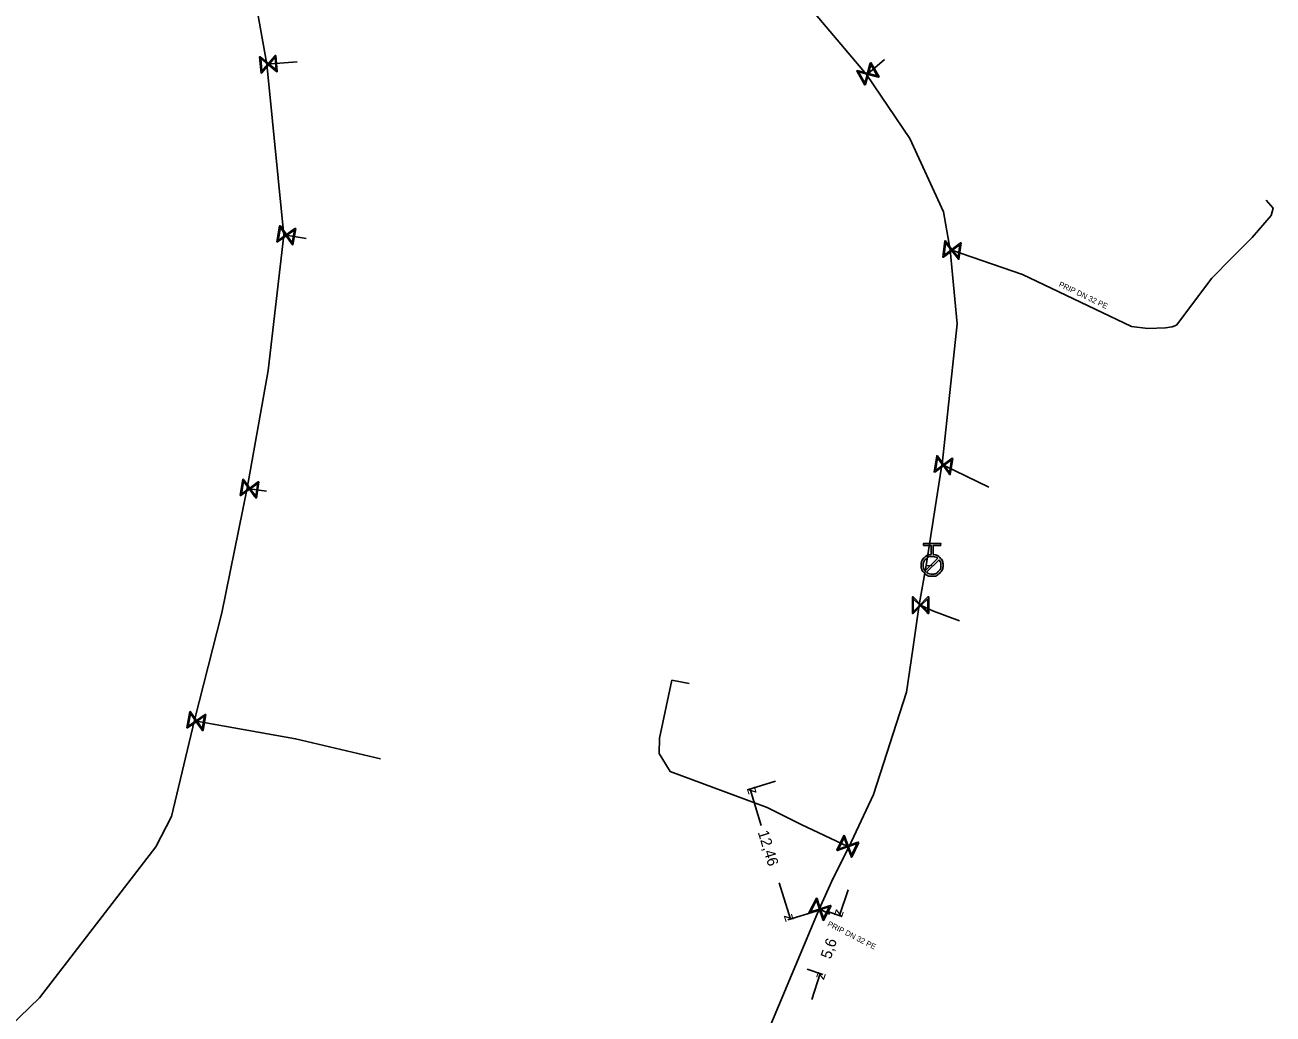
# Model space of a CAD drawing. Extents: x -641905 to -641246, y -1111750 to -1110210.
# Drawn here: x -641545.3 to -641431, y -1110496.2 to -1110405.6 of the extents above; entities that cross this region are included whole.
import ezdxf

# ---------------------------------------------------------------- set-up
doc = ezdxf.new("R2010")
doc.units = 0
for name, color, linetype in [('Default', 7, 'Continuous'), ('VP Hydrant', 7, 'Continuous'), ('VP Kótování', 7, 'Continuous'), ('VP Popis přípojky', 7, 'Continuous'), ('VP Přípojka', 7, 'Continuous'), ('VP Řad', 7, 'Continuous'), ('VP Šoupě', 7, 'Continuous')]:
    doc.layers.add(name, color=color, linetype=linetype)

msp = doc.modelspace()

# ---------------------------------------------------------------- linework, layer by layer
at = {"layer": 'Default'}
for points in [[(-641462.15, -1110454.13), (-641461.79, -1110454.16), (-641461.53, -1110454.43), (-641461.24, -1110454.72), (-641461.24, -1110455.13), (-641461.24, -1110455.55), (-641461.54, -1110455.84), (-641461.83, -1110456.13), (-641462.24, -1110456.13), (-641462.66, -1110456.13), (-641462.95, -1110455.84), (-641463.24, -1110455.54), (-641463.24, -1110455.13), (-641463.24, -1110454.71), (-641462.95, -1110454.42), (-641462.69, -1110454.16), (-641462.33, -1110454.13)], [(-641461.73, -1110454.49), (-641461.95, -1110454.32), (-641462.24, -1110454.32), (-641462.58, -1110454.32), (-641462.82, -1110454.55), (-641463.05, -1110454.79), (-641463.05, -1110455.13), (-641463.06, -1110455.42), (-641462.88, -1110455.64)], [(-641462.75, -1110455.77), (-641462.53, -1110455.94), (-641462.24, -1110455.94), (-641461.91, -1110455.94), (-641461.67, -1110455.71), (-641461.43, -1110455.47), (-641461.43, -1110455.13), (-641461.43, -1110454.84), (-641461.6, -1110454.62)]]:
    msp.add_open_spline(points, degree=3, dxfattribs=at)
at = {"layer": 'VP Hydrant'}
for points in [[(-641462.33, -1110454.13), (-641462.33, -1110453.31), (-641463.02, -1110453.31), (-641463.02, -1110453.13), (-641461.45, -1110453.13), (-641461.46, -1110453.32), (-641462.14, -1110453.31), (-641462.15, -1110454.13)], [(-641462.88, -1110455.64), (-641461.73, -1110454.49)], [(-641461.6, -1110454.62), (-641462.75, -1110455.77)]]:
    msp.add_lwpolyline(points, dxfattribs=at)
at = {"layer": 'VP Kótování'}
for points in [[(-641476.58, -1110474.91), (-641479.16, -1110475.71)], [(-641477.89, -1110478.95), (-641478.92, -1110475.64)], [(-641476.25, -1110484.22), (-641475.22, -1110487.54)], [(-641469.92, -1110484.84), (-641470.71, -1110487.22)], [(-641472.87, -1110486.8), (-641475.46, -1110487.61)], [(-641471.92, -1110486.81), (-641470.47, -1110487.29)], [(-641473.69, -1110492.13), (-641472.24, -1110492.61)], [(-641473.27, -1110494.9), (-641472.48, -1110492.53)]]:
    msp.add_lwpolyline(points, dxfattribs=at)
at = {"layer": 'VP Přípojka'}
for points in [[(-641523.18, -1110409.24), (-641520.39, -1110409.01)], [(-641468.24, -1110410.18), (-641468.12, -1110410.11), (-641466.6, -1110408.8)], [(-641460.59, -1110426.23), (-641460.43, -1110426.25), (-641453.95, -1110428.49), (-641443.99, -1110433.26), (-641442.49, -1110433.43), (-641440.85, -1110433.38), (-641440.25, -1110433.29), (-641439.86, -1110433.14), (-641436.63, -1110428.84), (-641434.77, -1110426.97), (-641432.91, -1110425.09), (-641431.17, -1110423.09), (-641431.01, -1110422.43), (-641431.64, -1110421.69)], [(-641521.61, -1110424.89), (-641521.4, -1110424.89), (-641519.58, -1110425.21)], [(-641461.34, -1110445.94), (-641461.2, -1110445.96), (-641457.03, -1110447.96)], [(-641524.97, -1110448.07), (-641524.76, -1110448.11), (-641523.22, -1110448.35)], [(-641462.79, -1110455.16), (-641462.57, -1110455.17)], [(-641462.57, -1110455.17), (-641462.24, -1110455.13)], [(-641463.43, -1110458.76), (-641463.3, -1110458.78), (-641462.11, -1110459.33), (-641459.72, -1110460.23)], [(-641469.87, -1110480.96), (-641469.96, -1110480.87), (-641474.22, -1110478.87), (-641477.36, -1110477.31), (-641486.22, -1110474.02), (-641487.25, -1110472.37), (-641487.2, -1110470.95), (-641486.07, -1110465.66), (-641484.49, -1110465.96)], [(-641529.81, -1110469.31), (-641529.63, -1110469.4), (-641520.55, -1110471.02), (-641512.77, -1110472.85)], [(-641472.59, -1110486.61), (-641472.51, -1110486.64), (-641471.61, -1110487.09)]]:
    msp.add_lwpolyline(points, dxfattribs=at)
at = {"layer": 'VP Řad'}
for points in [[(-641501.23, -1110373.51), (-641501.1, -1110373.66), (-641500.78, -1110374.02), (-641492.67, -1110383.28), (-641489.03, -1110387.57), (-641480.69, -1110396.36), (-641479.24, -1110398.03), (-641472.94, -1110404.61), (-641468.24, -1110410.18), (-641464.28, -1110416.05), (-641461.19, -1110422.75), (-641460.59, -1110426.23), (-641459.94, -1110433), (-641461.33, -1110445.88), (-641461.34, -1110445.94), (-641462.79, -1110455.16), (-641463.43, -1110458.76), (-641464.01, -1110462.8), (-641464.58, -1110466.76), (-641467.61, -1110476.11), (-641469.87, -1110480.96), (-641471.29, -1110483.79), (-641472.59, -1110486.61)], [(-641664.58, -1110640.46), (-641633.71, -1110609.9), (-641600.63, -1110563.76), (-641598.45, -1110560.36), (-641594.73, -1110553.8), (-641592.83, -1110550.42), (-641585.04, -1110537.85), (-641581.85, -1110531.99), (-641576.72, -1110525.41), (-641572.32, -1110520.62), (-641569.27, -1110517.47), (-641555.1, -1110505.43), (-641544.01, -1110494.76), (-641533.36, -1110480.93), (-641531.9, -1110478.13), (-641529.81, -1110469.31), (-641527.31, -1110459.48), (-641524.97, -1110448.07), (-641523.07, -1110437.29), (-641521.61, -1110424.89), (-641523.18, -1110409.24), (-641525.76, -1110394.87), (-641527.66, -1110384.33)], [(-641472.59, -1110486.61), (-641478.05, -1110499.66), (-641479.43, -1110506.37), (-641479.47, -1110506.59)]]:
    msp.add_lwpolyline(points, dxfattribs=at)
at = {"layer": 'VP Šoupě'}
for points in [[(-641522.35, -1110408.42), (-641522.22, -1110409.91), (-641522.29, -1110409.92), (-641522.38, -1110409.83), (-641523.02, -1110409.29), (-641523.65, -1110410.03), (-641523.71, -1110410.04), (-641523.84, -1110408.55), (-641523.78, -1110408.54), (-641523.03, -1110409.17), (-641522.49, -1110408.53), (-641522.41, -1110408.42), (-641522.35, -1110408.42)], [(-641523.63, -1110409.88), (-641523.09, -1110409.24), (-641523.73, -1110408.69), (-641523.63, -1110409.88)], [(-641522.43, -1110408.58), (-641522.97, -1110409.23), (-641522.33, -1110409.76), (-641522.43, -1110408.58)], [(-641467.85, -1110409.08), (-641467.09, -1110410.38), (-641467.15, -1110410.41), (-641467.27, -1110410.38), (-641468.09, -1110410.16), (-641468.33, -1110411.1), (-641468.39, -1110411.14), (-641469.15, -1110409.84), (-641469.09, -1110409.81), (-641468.15, -1110410.06), (-641467.94, -1110409.24), (-641467.91, -1110409.12), (-641467.85, -1110409.08)], [(-641468.39, -1110410.96), (-641468.17, -1110410.14), (-641468.99, -1110409.93), (-641468.39, -1110410.96)], [(-641467.85, -1110409.27), (-641468.06, -1110410.08), (-641467.26, -1110410.29), (-641467.85, -1110409.27)], [(-641520.53, -1110424.28), (-641520.79, -1110425.76), (-641520.85, -1110425.75), (-641520.93, -1110425.64), (-641521.41, -1110424.95), (-641522.2, -1110425.51), (-641522.27, -1110425.5), (-641522.01, -1110424.02), (-641521.94, -1110424.03), (-641521.39, -1110424.83), (-641520.7, -1110424.35), (-641520.6, -1110424.27), (-641520.53, -1110424.28)], [(-641522.15, -1110425.37), (-641521.46, -1110424.88), (-641521.94, -1110424.19), (-641522.15, -1110425.37)], [(-641520.65, -1110424.42), (-641521.34, -1110424.9), (-641520.85, -1110425.59), (-641520.65, -1110424.42)], [(-641459.59, -1110425.6), (-641459.78, -1110427.09), (-641459.84, -1110427.08), (-641459.92, -1110426.97), (-641460.44, -1110426.31), (-641461.2, -1110426.91), (-641461.27, -1110426.9), (-641461.08, -1110425.41), (-641461.02, -1110425.42), (-641460.42, -1110426.19), (-641459.76, -1110425.67), (-641459.66, -1110425.59), (-641459.59, -1110425.6)], [(-641461.15, -1110426.76), (-641460.49, -1110426.24), (-641461.01, -1110425.58), (-641461.15, -1110426.76)], [(-641459.7, -1110425.74), (-641460.37, -1110426.26), (-641459.85, -1110426.92), (-641459.7, -1110425.74)], [(-641460.34, -1110445.34), (-641460.58, -1110446.82), (-641460.64, -1110446.81), (-641460.71, -1110446.7), (-641461.21, -1110446.02), (-641461.99, -1110446.59), (-641462.06, -1110446.58), (-641461.82, -1110445.1), (-641461.76, -1110445.11), (-641461.19, -1110445.9), (-641460.51, -1110445.4), (-641460.41, -1110445.33), (-641460.34, -1110445.34)], [(-641461.94, -1110446.45), (-641461.26, -1110445.95), (-641461.76, -1110445.27), (-641461.94, -1110446.45)], [(-641460.46, -1110445.48), (-641461.14, -1110445.97), (-641460.64, -1110446.65), (-641460.46, -1110445.48)], [(-641523.9, -1110447.49), (-641524.14, -1110448.97), (-641524.2, -1110448.96), (-641524.27, -1110448.85), (-641524.77, -1110448.17), (-641525.55, -1110448.74), (-641525.62, -1110448.73), (-641525.38, -1110447.25), (-641525.32, -1110447.26), (-641524.75, -1110448.05), (-641524.07, -1110447.55), (-641523.97, -1110447.48), (-641523.9, -1110447.49)], [(-641525.5, -1110448.6), (-641524.82, -1110448.1), (-641525.32, -1110447.42), (-641525.5, -1110448.6)], [(-641524.02, -1110447.63), (-641524.7, -1110448.12), (-641524.2, -1110448.8), (-641524.02, -1110447.63)], [(-641462.55, -1110458.03), (-641462.55, -1110459.53), (-641462.62, -1110459.53), (-641462.7, -1110459.44), (-641463.3, -1110458.84), (-641463.98, -1110459.53), (-641464.05, -1110459.53), (-641464.05, -1110458.03), (-641463.98, -1110458.03), (-641463.3, -1110458.72), (-641462.71, -1110458.12), (-641462.62, -1110458.03), (-641462.55, -1110458.03)], [(-641463.96, -1110459.38), (-641463.36, -1110458.78), (-641463.96, -1110458.19), (-641463.96, -1110459.38)], [(-641462.64, -1110458.19), (-641463.24, -1110458.78), (-641462.64, -1110459.37), (-641462.64, -1110458.19)], [(-641528.76, -1110468.79), (-641529.02, -1110470.27), (-641529.09, -1110470.26), (-641529.16, -1110470.15), (-641529.64, -1110469.46), (-641530.44, -1110470.02), (-641530.5, -1110470.01), (-641530.24, -1110468.53), (-641530.17, -1110468.54), (-641529.62, -1110469.34), (-641528.93, -1110468.86), (-641528.82, -1110468.78), (-641528.76, -1110468.79)], [(-641530.38, -1110469.87), (-641529.69, -1110469.39), (-641530.17, -1110468.7), (-641530.38, -1110469.87)], [(-641528.88, -1110468.93), (-641529.57, -1110469.41), (-641529.09, -1110470.1), (-641528.88, -1110468.93)], [(-641468.96, -1110480.51), (-641469.6, -1110481.87), (-641469.66, -1110481.84), (-641469.7, -1110481.72), (-641469.99, -1110480.93), (-641470.9, -1110481.26), (-641470.96, -1110481.23), (-641470.32, -1110479.87), (-641470.26, -1110479.9), (-641469.93, -1110480.82), (-641469.14, -1110480.53), (-641469.02, -1110480.48), (-641468.96, -1110480.51)], [(-641470.81, -1110481.13), (-641470.02, -1110480.85), (-641470.3, -1110480.05), (-641470.81, -1110481.13)], [(-641469.11, -1110480.61), (-641469.9, -1110480.9), (-641469.62, -1110481.69), (-641469.11, -1110480.61)], [(-641471.5, -1110486.31), (-641472.18, -1110487.65), (-641472.24, -1110487.62), (-641472.27, -1110487.49), (-641472.54, -1110486.7), (-641473.46, -1110487), (-641473.52, -1110486.97), (-641472.84, -1110485.63), (-641472.78, -1110485.66), (-641472.48, -1110486.59), (-641471.68, -1110486.32), (-641471.56, -1110486.28), (-641471.5, -1110486.31)], [(-641473.37, -1110486.88), (-641472.56, -1110486.61), (-641472.83, -1110485.81), (-641473.37, -1110486.88)], [(-641471.66, -1110486.41), (-641472.45, -1110486.67), (-641472.19, -1110487.46), (-641471.66, -1110486.41)]]:
    msp.add_lwpolyline(points, dxfattribs=at)

# ---------------------------------------------------------------- texts
at = {"layer": 'VP Kótování'}
for s, rotation, p in [('z', 107.306, (-641478.3, -1110475.97)), ('12,46', 287.306, (-641478.22, -1110479.58)), ('z', 251.6118, (-641471.03, -1110486.58)), ('z', 287.306, (-641475.84, -1110487.21)), ('5,6', 71.6118, (-641471.53, -1110491.26)), ('z', 71.6118, (-641472.16, -1110493.16))]:
    msp.add_text(s, height=1, rotation=rotation, dxfattribs=at).set_placement(p)
at = {"layer": 'VP Popis přípojky'}
for rotation, p in [(334.4095, (-641450.69, -1110429.56)), (333.1546, (-641471.88, -1110488.14))]:
    msp.add_text('PRIP DN 32 PE', height=0.5, rotation=rotation, dxfattribs=at).set_placement(p)

doc.saveas('drawing.dxf')
